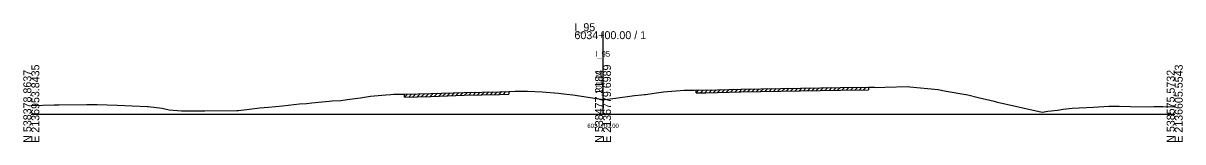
# Model space of a CAD drawing. Extents: x -12534 to 3403, y -1332 to 21983.
# Drawn here: x 997.2 to 1402.8, y 18990.3 to 19032 of the extents above; entities that cross this region are included whole.
import ezdxf

# ---------------------------------------------------------------- set-up
doc = ezdxf.new("R2010")
doc.units = 0
for name, color, linetype in [('RD_GPK_XS_Cell', 7, 'Continuous'), ('RD_XS_ExGround', 7, 'Continuous'), ('RD_XS_ExPaveRet', 7, 'Continuous'), ('RD_XS_TX_Baseline', 7, 'Continuous'), ('RD_XS_TX_Elev_EX', 7, 'Continuous'), ('RD_XS_TX_Station', 7, 'Continuous')]:
    doc.layers.add(name, color=color, linetype=linetype)

msp = doc.modelspace()

# ---------------------------------------------------------------- linework, layer by layer
at = {"layer": 'RD_GPK_XS_Cell'}
for p, q in [((1200, 19000), (1200, 19029.2)), ((1000, 19000), (1200, 19000)), ((1200, 19000), (1400, 19000))]:
    msp.add_line(p, q, dxfattribs=at)
at = {"layer": 'RD_XS_ExGround'}
msp.add_lwpolyline([(1000, 19003.09), (1007.99, 19003.31), (1009.67, 19003.33), (1019.48, 19003.43), (1023.05, 19003.43), (1030.07, 19003.26), (1040.56, 19002.77), (1040.89, 19002.73), (1045.74, 19002.11), (1048.24, 19001.57), (1052.55, 19001.2), (1060.76, 19001.22), (1071.91, 19001.28), (1072.46, 19001.31), (1079.9, 19002.23), (1083.02, 19002.48), (1087.85, 19002.96), (1093.85, 19003.67), (1096.29, 19003.84), (1098.19, 19004.01), (1101.65, 19004.36), (1104.21, 19004.59), (1105.23, 19004.68), (1108.31, 19004.9), (1110.45, 19005.15), (1115.18, 19005.8), (1118.7, 19006.32), (1119.92, 19006.48), (1124, 19006.82), (1125.72, 19007), (1126.76, 19007.02), (1130.08, 19007.03), (1130.52, 19007.03), (1139.77, 19007.3), (1151.42, 19007.69), (1163.8, 19007.94), (1167.02, 19008.04), (1169.22, 19008.17), (1173.59, 19008.13), (1178.69, 19007.93), (1184.48, 19007.4), (1187.27, 19007.12), (1189.44, 19006.81), (1199.41, 19005.29), (1200, 19005.22), (1200.31, 19005.18), (1200.65, 19005.22), (1204.36, 19005.68), (1210.99, 19006.6), (1213.45, 19006.82), (1214.54, 19006.92), (1214.88, 19006.97), (1218.67, 19007.56), (1221.22, 19007.94), (1228.38, 19008.47), (1230.42, 19008.48), (1231.88, 19008.53), (1232.59, 19008.54), (1236.03, 19008.52), (1248.24, 19008.85), (1283.07, 19009.46), (1292.92, 19009.56), (1294.94, 19009.51), (1295.81, 19009.45), (1298.65, 19009.54), (1306.82, 19009.73), (1307.36, 19009.68), (1317.28, 19008.67), (1320.07, 19008.18), (1327.68, 19006.83), (1331.22, 19005.96), (1336.87, 19004.59), (1337.52, 19004.42), (1337.96, 19004.32), (1353.63, 19000.81), (1355.62, 19001.06), (1358.97, 19001.5), (1360.97, 19001.77), (1364.14, 19002.18), (1371.54, 19002.46), (1376.93, 19002.82), (1380.59, 19002.81), (1384.58, 19002.8), (1391.6, 19002.68), (1392.75, 19002.69), (1395.89, 19002.69), (1400, 19002.68)], dxfattribs=at)
at = {"layer": 'RD_XS_ExPaveRet'}
for p, q in [((1130.52, 19006.03), (1131.55, 19007.06)), ((1130.52, 19006.03), (1130.52, 19007.03)), ((1130.52, 19006.03), (1139.77, 19006.3)), ((1132.02, 19006.07), (1133.05, 19007.1)), ((1133.52, 19006.12), (1134.55, 19007.15)), ((1135.02, 19006.16), (1136.05, 19007.19)), ((1136.52, 19006.21), (1137.55, 19007.24)), ((1138.02, 19006.25), (1139.05, 19007.28)), ((1139.52, 19006.29), (1140.56, 19007.33)), ((1139.77, 19006.3), (1151.42, 19006.69)), ((1141.02, 19006.34), (1142.06, 19007.38)), ((1142.52, 19006.39), (1143.56, 19007.43)), ((1144.02, 19006.44), (1145.06, 19007.48)), ((1145.52, 19006.49), (1146.56, 19007.53)), ((1147.02, 19006.54), (1148.06, 19007.58)), ((1148.52, 19006.59), (1149.56, 19007.63)), ((1150.02, 19006.64), (1151.06, 19007.68)), ((1151.42, 19006.69), (1163.8, 19006.94)), ((1151.52, 19006.69), (1152.54, 19007.71)), ((1153.02, 19006.72), (1154.04, 19007.74)), ((1154.52, 19006.75), (1155.54, 19007.77)), ((1156.02, 19006.78), (1157.04, 19007.8)), ((1157.52, 19006.81), (1158.54, 19007.83)), ((1159.02, 19006.84), (1160.04, 19007.86)), ((1160.52, 19006.87), (1161.54, 19007.89)), ((1162.02, 19006.9), (1163.04, 19007.92)), ((1163.52, 19006.93), (1164.55, 19007.96)), ((1163.8, 19006.94), (1167.02, 19007.04)), ((1165.02, 19006.98), (1166.06, 19008.01)), ((1167.02, 19008.04), (1167.02, 19007.04)), ((1232.59, 19007.54), (1233.58, 19008.54)), ((1232.59, 19007.54), (1232.59, 19008.54)), ((1232.59, 19007.54), (1236.03, 19007.52)), ((1234.09, 19007.53), (1235.08, 19008.53)), ((1235.59, 19007.53), (1236.6, 19008.54)), ((1236.03, 19007.52), (1248.24, 19007.85)), ((1237.09, 19007.55), (1238.12, 19008.58)), ((1238.59, 19007.59), (1239.62, 19008.62)), ((1240.09, 19007.63), (1241.12, 19008.66)), ((1241.59, 19007.67), (1242.62, 19008.7)), ((1243.09, 19007.71), (1244.12, 19008.74)), ((1244.59, 19007.75), (1245.62, 19008.78)), ((1246.09, 19007.79), (1247.12, 19008.82)), ((1247.59, 19007.83), (1248.61, 19008.86)), ((1248.24, 19007.85), (1283.07, 19008.46)), ((1249.09, 19007.86), (1250.11, 19008.88)), ((1250.59, 19007.89), (1251.61, 19008.91)), ((1252.09, 19007.92), (1253.11, 19008.93)), ((1253.59, 19007.94), (1254.61, 19008.96)), ((1255.09, 19007.97), (1256.11, 19008.99)), ((1256.59, 19008), (1257.61, 19009.01)), ((1258.09, 19008.02), (1259.11, 19009.04)), ((1259.59, 19008.05), (1260.61, 19009.07)), ((1261.09, 19008.07), (1262.11, 19009.09)), ((1262.59, 19008.1), (1263.61, 19009.12)), ((1264.09, 19008.13), (1265.11, 19009.15)), ((1265.59, 19008.15), (1266.61, 19009.17)), ((1267.09, 19008.18), (1268.11, 19009.2)), ((1268.59, 19008.21), (1269.61, 19009.22)), ((1270.09, 19008.23), (1271.11, 19009.25)), ((1271.59, 19008.26), (1272.61, 19009.28)), ((1273.09, 19008.29), (1274.11, 19009.3)), ((1274.59, 19008.31), (1275.61, 19009.33)), ((1276.09, 19008.34), (1277.11, 19009.36)), ((1277.59, 19008.36), (1278.61, 19009.38)), ((1279.09, 19008.39), (1280.11, 19009.41)), ((1280.59, 19008.42), (1281.61, 19009.44)), ((1282.09, 19008.44), (1283.11, 19009.46)), ((1283.07, 19008.46), (1292.92, 19008.56)), ((1283.59, 19008.47), (1284.6, 19009.48)), ((1285.09, 19008.48), (1286.1, 19009.49)), ((1286.59, 19008.5), (1287.6, 19009.51)), ((1288.09, 19008.51), (1289.1, 19009.52)), ((1289.59, 19008.53), (1290.6, 19009.54)), ((1291.09, 19008.54), (1292.1, 19009.55)), ((1292.92, 19009.56), (1292.92, 19008.56))]:
    msp.add_line(p, q, dxfattribs=at)

# ---------------------------------------------------------------- texts
at = {"layer": 'RD_GPK_XS_Cell'}
for s, p in [('I_95', (1190, 19029.2)), ('6034+00.00 / 1', (1190, 19026.4))]:
    msp.add_text(s, height=2.8, dxfattribs=at).set_placement(p)
for s, p in [('N 538378.8637', (1000, 18990)), ('E 2136953.8435', (1002.8, 18990)), ('N 538477.2184', (1200, 18990)), ('E 2136779.6989', (1202.8, 18990)), ('N 538575.5732', (1400, 18990)), ('E 2136605.5543', (1402.8, 18990))]:
    msp.add_text(s, height=2.8, rotation=90, dxfattribs=at).set_placement(p)
at = {"layer": 'RD_XS_TX_Baseline'}
msp.add_text('I_95', height=2, dxfattribs=at).set_placement((1197.28, 19020.22))
at = {"layer": 'RD_XS_TX_Elev_EX'}
msp.add_text('101.22', height=2, rotation=90, dxfattribs=at).set_placement((1199.5, 19007.22))
at = {"layer": 'RD_XS_TX_Station'}
msp.add_text('6034+00.00', height=1.5, dxfattribs=at).set_placement((1194.53, 18995.22))

doc.saveas('drawing.dxf')
